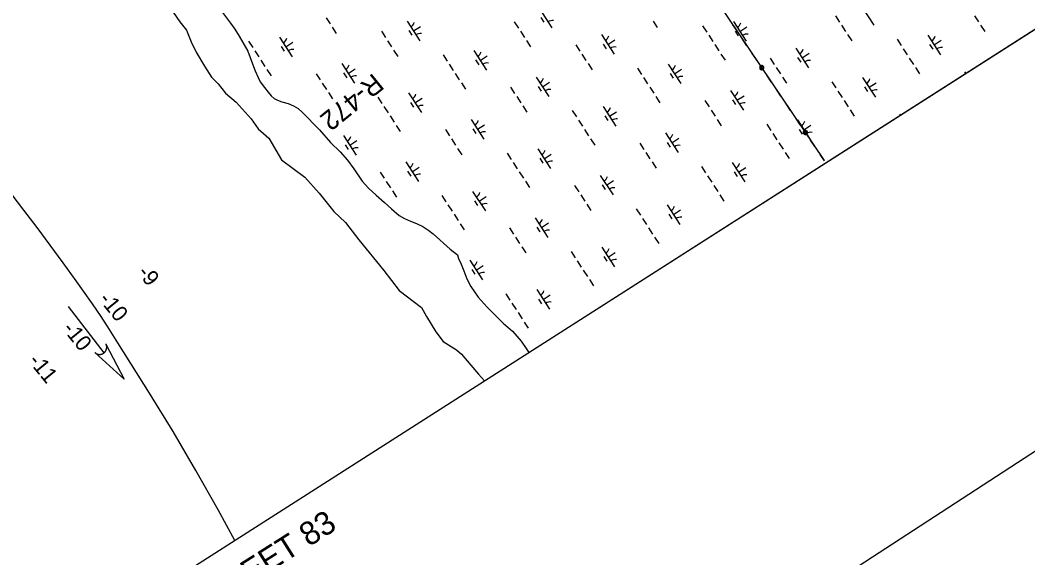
# Model space of a CAD drawing. Extents: x 3953924 to 3974542, y 193747 to 216192.
# Drawn here: x 3968214 to 3970369, y 198304 to 199454 of the extents above; entities that cross this region are included whole.
import ezdxf

# ---------------------------------------------------------------- set-up
doc = ezdxf.new("R2010")
doc.units = 0
for name, color, linetype in [('V-ANNO-SYMB', 7, 'Continuous'), ('V-ANNO-TEXT', 7, 'Continuous'), ('V-GRID-FRAM', 7, 'Continuous'), ('V-RIVR-EDGE', 7, 'Continuous'), ('V-RIVR-RANG', 7, 'Continuous'), ('V-RIVR-RANG-IDEN', 7, 'Continuous'), ('V-STRM-FLOW', 7, 'Continuous'), ('V-TOPO-MINR', 7, 'Continuous'), ('V-UTIL-LINE', 7, 'Continuous'), ('V-WETL-SWMP', 7, 'Continuous')]:
    doc.layers.add(name, color=color, linetype=linetype)

msp = doc.modelspace()

# ---------------------------------------------------------------- linework, layer by layer
at = {"layer": 'V-ANNO-SYMB'}
msp.add_lwpolyline([(3955180.9, 208373.9), (3964205.1, 194510.7), (3973808.1, 200761.7), (3964783.9, 214624.9), (3955180.9, 208373.9)], dxfattribs=at)
at = {"layer": 'V-GRID-FRAM'}
msp.add_lwpolyline([(3964669.3, 213787.9), (3972946, 201072.9), (3966057, 196668.5), (3957950.8, 209463.9), (3964669.3, 213787.9)], dxfattribs=at)
at = {"layer": 'V-RIVR-EDGE'}
msp.add_lwpolyline([(3968541.4, 199470.9), (3968555.6, 199450.7), (3968569.9, 199432.9), (3968579.4, 199408), (3968590, 199385.4), (3968607.8, 199355.7), (3968623.3, 199332), (3968637.5, 199317.7), (3968653, 199297.6), (3968675.5, 199278.6), (3968707.6, 199242.9), (3968723, 199221.6), (3968745.6, 199201.4), (3968772.9, 199155.1), (3968822.7, 199118.3), (3968853.6, 199083.9), (3968884.5, 199044.7), (3968909.4, 199020.9), (3968937.9, 198984.1), (3968991.3, 198918.8), (3969024.6, 198876.1), (3969072, 198839.3), (3969082.7, 198820.3), (3969102.9, 198787.1), (3969118.4, 198766.9), (3969146.8, 198749.1), (3969157.5, 198739.6), (3969177.7, 198715.8), (3969194.3, 198696.8), (3969206.8, 198682.3)], dxfattribs=at)
at = {"layer": 'V-STRM-FLOW'}
msp.add_line((3968316.7, 198841.5), (3968393, 198742.3), dxfattribs=at)
msp.add_lwpolyline([(3968397.3, 198761.3), (3968436.2, 198686.1), (3968373.5, 198743), (3968374.7, 198742.1), (3968375.9, 198741.2), (3968376.4, 198741), (3968376.9, 198740.7), (3968377.5, 198740.4), (3968378, 198740.2), (3968378.5, 198740), (3968379.2, 198739.8), (3968380, 198739.6), (3968380.4, 198739.5), (3968380.9, 198739.4), (3968381.7, 198739.2), (3968382.2, 198739.2), (3968382.8, 198739.1), (3968383.2, 198739.1), (3968383.7, 198739.1), (3968384.2, 198739.1), (3968384.7, 198739.1), (3968385.2, 198739.2), (3968385.7, 198739.2), (3968386.3, 198739.3), (3968386.8, 198739.4), (3968387.3, 198739.5), (3968387.8, 198739.7), (3968388.3, 198739.8), (3968388.7, 198739.9), (3968389, 198740), (3968389.5, 198740.2), (3968389.9, 198740.4), (3968390.4, 198740.6), (3968390.8, 198740.8), (3968391.2, 198741.1), (3968391.7, 198741.3), (3968392, 198741.5), (3968392.5, 198741.9), (3968393, 198742.3), (3968393.2, 198742.4), (3968393.4, 198742.6), (3968393.7, 198742.8), (3968394, 198743.1), (3968394.2, 198743.3), (3968394.5, 198743.5), (3968394.8, 198743.8), (3968394.9, 198744), (3968395.2, 198744.3), (3968395.5, 198744.6), (3968395.6, 198744.8), (3968396, 198745.3), (3968396.2, 198745.6), (3968396.4, 198745.8), (3968396.6, 198746.2), (3968396.8, 198746.5), (3968397, 198746.8), (3968397.2, 198747.2), (3968397.4, 198747.6), (3968397.5, 198747.9), (3968397.7, 198748.1), (3968397.8, 198748.5), (3968397.9, 198748.8), (3968398.1, 198749.2), (3968398.2, 198749.6), (3968398.3, 198749.9), (3968398.5, 198750.4), (3968398.6, 198750.8), (3968398.7, 198751.2), (3968398.7, 198751.6), (3968398.8, 198751.9), (3968398.8, 198752.3), (3968398.9, 198752.8), (3968398.9, 198752.8), (3968398.9, 198753.1), (3968398.9, 198753.3), (3968399, 198753.7), (3968399, 198754.1), (3968399, 198754.4), (3968399, 198754.8), (3968399, 198755.1), (3968398.9, 198755.5), (3968398.9, 198755.8), (3968398.9, 198756.1), (3968398.8, 198756.6), (3968398.8, 198756.9), (3968398.7, 198757.1), (3968398.7, 198757.3), (3968398.6, 198757.6), (3968398.6, 198757.9), (3968398.5, 198758.2), (3968398.4, 198758.5), (3968398.3, 198758.8), (3968398.2, 198759.2), (3968398.1, 198759.5), (3968398, 198759.8), (3968397.8, 198760.3), (3968397.6, 198760.6), (3968397.5, 198760.8), (3968397.4, 198761), (3968397.4, 198761.2)], close=True, dxfattribs=at)
at = {"layer": 'V-TOPO-MINR'}
msp.add_lwpolyline([(3968672.8, 198340.9), (3968637.2, 198406.4), (3968589.9, 198490.7), (3968540.8, 198573.9), (3968490.5, 198656.4), (3968423.1, 198764.1), (3968405.3, 198792.1), (3968387.1, 198819.8), (3968368.5, 198847.1), (3968349.5, 198874.3), (3968333.5, 198896.7), (3968306, 198934.8), (3968278.4, 198972.7), (3968250.3, 199010.3), (3968222.1, 199047.8), (3967951.2, 199403.4)], dxfattribs=at)
at = {"layer": 'V-UTIL-LINE'}
for points in [[(3969933.5, 199153.6), (3965324.7, 205998.6), (3961472.6, 211752)], [(3969747.5, 199429.9), (3969738, 199444)], [(3969768.1, 199399.2), (3969758.6, 199413.3)], [(3969788.8, 199368.5), (3969779.3, 199382.6)], [(3969799.7, 199352.4), (3969799.2, 199351), (3969800.3, 199351.3), (3969800.8, 199352.6), (3969799.8, 199353.7), (3969798.4, 199352.8), (3969797.9, 199350.5), (3969799.7, 199349.4), (3969802, 199350.2), (3969802.5, 199352.4), (3969801.7, 199354.5), (3969799.4, 199355.2), (3969797, 199353.8), (3969795.9, 199349.8), (3969797.2, 199348.6), (3969798.8, 199347.9), (3969800.6, 199347.9), (3969802.2, 199348.6), (3969803.4, 199349.9), (3969804.1, 199351.5), (3969804.1, 199353.2), (3969803.4, 199354.9), (3969802.2, 199356.1), (3969800.5, 199356.8), (3969798.8, 199356.8), (3969797.2, 199356.1), (3969795.9, 199354.8), (3969795.3, 199353.2), (3969795.3, 199351.5), (3969795.9, 199349.8)], [(3969820.1, 199322.1), (3969810.6, 199336.2)], [(3969840.7, 199291.4), (3969831.2, 199305.5)], [(3969861.4, 199260.7), (3969851.9, 199274.8)], [(3969882.1, 199230), (3969872.6, 199244.1)], [(3969893, 199213.8), (3969892.4, 199212.5), (3969893.6, 199212.8), (3969894, 199214.1), (3969893.1, 199215.2), (3969891.6, 199214.3), (3969891.1, 199212), (3969892.9, 199210.9), (3969895.2, 199211.7), (3969895.8, 199213.9), (3969895, 199216), (3969892.7, 199216.6), (3969890.3, 199215.2), (3969889.2, 199211.3), (3969890.5, 199210.1), (3969892.1, 199209.4), (3969893.8, 199209.4), (3969895.5, 199210.1), (3969896.7, 199211.3), (3969897.4, 199213), (3969897.4, 199214.7), (3969896.7, 199216.3), (3969895.4, 199217.6), (3969893.8, 199218.2), (3969892.1, 199218.2), (3969890.4, 199217.6), (3969889.2, 199216.3), (3969888.5, 199214.7), (3969888.5, 199212.9), (3969889.2, 199211.3)], [(3969913.3, 199183.5), (3969903.8, 199197.6)], [(3969934, 199152.9), (3969924.5, 199167)]]:
    msp.add_lwpolyline(points, dxfattribs=at)
at = {"layer": 'V-WETL-SWMP'}
for p, q in [((3969301.7, 198743), (3972946, 201072.9)), ((3968646.4, 199470.3), (3968663.9, 199447.8)), ((3969323.4, 199479.7), (3969350.6, 199437.8)), ((3970011.9, 199485), (3970039.2, 199443.1)), ((3968663.9, 199447.8), (3968673, 199435.1)), ((3968868, 199459.4), (3968876.7, 199446)), ((3969041.1, 199452), (3969068.3, 199410.1)), ((3969270.6, 199450.7), (3969279.4, 199437.3)), ((3969327.3, 199459.6), (3969333.8, 199449.6)), ((3969567.6, 199452), (3969576.3, 199438.6)), ((3969739.1, 199450.9), (3969766.3, 199409)), ((3969957.1, 199463.4), (3969965.9, 199450)), ((3969970.2, 199443.3), (3969979, 199429.8)), ((3970254.6, 199463.7), (3970263.3, 199450.3)), ((3970267.6, 199443.6), (3970276.4, 199430.1)), ((3968673, 199435.1), (3968682.1, 199419.5)), ((3968881.1, 199439.3), (3968889.8, 199425.9)), ((3968986.3, 199430.3), (3968995, 199416.9)), ((3969045, 199431.8), (3969051.5, 199421.8)), ((3969054.7, 199431), (3969069.8, 199440.8)), ((3969283.7, 199430.6), (3969292.4, 199417.2)), ((3969456.8, 199423.1), (3969484.1, 199381.2)), ((3969673.3, 199442), (3969682, 199428.6)), ((3969686.3, 199421.9), (3969695.1, 199408.5)), ((3969743, 199430.8), (3969749.5, 199420.7)), ((3969752.7, 199430), (3969767.8, 199439.8)), ((3969983.3, 199423.1), (3969992.1, 199409.7)), ((3970154.8, 199422.1), (3970182.1, 199380.2)), ((3968682.1, 199419.5), (3968700.4, 199387.6)), ((3968702.4, 199408.9), (3968711.1, 199395.5)), ((3968768.2, 199417.8), (3968795.5, 199375.9)), ((3968781.9, 199396.9), (3968797, 199406.7)), ((3968999.4, 199410.2), (3969008.1, 199396.8)), ((3969296.8, 199410.5), (3969305.5, 199397.1)), ((3969402, 199401.5), (3969410.7, 199388)), ((3969460.7, 199403), (3969467.2, 199392.9)), ((3969470.4, 199402.2), (3969485.5, 199412)), ((3969699.4, 199401.8), (3969708.2, 199388.3)), ((3970089, 199413.2), (3970097.7, 199399.7)), ((3970158.7, 199402), (3970165.2, 199391.9)), ((3970168.4, 199401.1), (3970183.5, 199411)), ((3968700.4, 199387.6), (3968706, 199374.3)), ((3968715.5, 199388.8), (3968724.2, 199375.4)), ((3968772.1, 199397.7), (3968778.7, 199387.6)), ((3969012.5, 199390.1), (3969021.2, 199376.6)), ((3969118.1, 199380.1), (3969126.9, 199366.7)), ((3969184, 199389), (3969211.2, 199347.1)), ((3969415.1, 199381.3), (3969423.8, 199367.9)), ((3969712.5, 199381.6), (3969721.3, 199368.2)), ((3969872.5, 199394.3), (3969899.8, 199352.4)), ((3969886.1, 199373.3), (3969901.2, 199383.2)), ((3970102.1, 199393), (3970110.8, 199379.6)), ((3968706, 199374.3), (3968710.4, 199360.9)), ((3968710.4, 199360.9), (3968716.6, 199345.7)), ((3968728.6, 199368.7), (3968737.3, 199355.3)), ((3968901.7, 199361.2), (3968928.9, 199319.3)), ((3969131.2, 199360), (3969140, 199346.5)), ((3969187.8, 199368.9), (3969194.4, 199358.8)), ((3969197.6, 199368.1), (3969212.7, 199377.9)), ((3969428.2, 199361.2), (3969436.9, 199347.8)), ((3969599.7, 199360.2), (3969626.9, 199318.3)), ((3969817.7, 199372.6), (3969826.5, 199359.2)), ((3969876.4, 199374.2), (3969882.9, 199364.1)), ((3970115.2, 199372.9), (3970123.9, 199359.5)), ((3968716.6, 199345.7), (3968722.8, 199331.2)), ((3968741.7, 199348.6), (3968750.4, 199335.2)), ((3968846.9, 199339.5), (3968855.6, 199326.1)), ((3968905.6, 199341.1), (3968912.1, 199331)), ((3968915.3, 199340.3), (3968930.4, 199350.1)), ((3969144.3, 199339.8), (3969153, 199326.4)), ((3969533.8, 199351.2), (3969542.6, 199337.8)), ((3969603.6, 199340), (3969610.1, 199330)), ((3969613.3, 199339.2), (3969628.4, 199349)), ((3969830.8, 199352.5), (3969839.6, 199339.1)), ((3970128.2, 199352.8), (3970137, 199339.4)), ((3970233.5, 199343.8), (3970235.8, 199340.2)), ((3968722.8, 199331.2), (3968727.1, 199322.5)), ((3968727.1, 199322.5), (3968736.2, 199309.8)), ((3968860, 199319.4), (3968868.7, 199306)), ((3969157.4, 199319.7), (3969166.1, 199306.3)), ((3969317.4, 199332.4), (3969344.6, 199290.5)), ((3969331, 199311.4), (3969346.1, 199321.3)), ((3969546.9, 199331.1), (3969555.7, 199317.7)), ((3969843.9, 199332.4), (3969852.7, 199319)), ((3969949.6, 199322.4), (3969958.3, 199309)), ((3970015.4, 199331.3), (3970042.7, 199289.4)), ((3970029, 199310.4), (3970044.1, 199320.2)), ((3968736.2, 199309.8), (3968744, 199300)), ((3968744, 199300), (3968750.6, 199292)), ((3968873.1, 199299.3), (3968881.8, 199285.9)), ((3969044.5, 199298.3), (3969071.8, 199256.4)), ((3969262.6, 199310.7), (3969271.3, 199297.3)), ((3969321.3, 199312.3), (3969327.8, 199302.2)), ((3969560, 199311), (3969568.8, 199297.6)), ((3969733.1, 199303.6), (3969760.4, 199261.7)), ((3969746.7, 199282.6), (3969761.8, 199292.4)), ((3969962.7, 199302.3), (3969971.4, 199288.9)), ((3970019.3, 199311.2), (3970025.8, 199301.2)), ((3968750.6, 199292), (3968757.2, 199286.8)), ((3968757.2, 199286.8), (3968764.3, 199282.9)), ((3968764.3, 199282.9), (3968773.2, 199279.6)), ((3968773.2, 199279.6), (3968786.8, 199275.8)), ((3968786.8, 199275.8), (3968798.6, 199270.7)), ((3968798.6, 199270.7), (3968808.1, 199265.1)), ((3968978.7, 199289.3), (3968987.5, 199275.9)), ((3969048.4, 199278.1), (3969055, 199268.1)), ((3969058.2, 199277.3), (3969073.3, 199287.1)), ((3969275.7, 199290.6), (3969284.4, 199277.2)), ((3969573.1, 199290.9), (3969581.9, 199277.5)), ((3969678.3, 199281.9), (3969687.1, 199268.5)), ((3969737, 199283.4), (3969743.5, 199273.4)), ((3969975.7, 199282.2), (3969984.5, 199268.8)), ((3968808.1, 199265.1), (3968817.1, 199257.1)), ((3968817.1, 199257.1), (3968854.3, 199219.2)), ((3968991.8, 199269.2), (3969000.5, 199255.8)), ((3969288.8, 199270.5), (3969297.5, 199257.1)), ((3969394.4, 199260.5), (3969403.2, 199247.1)), ((3969460.3, 199269.4), (3969487.5, 199227.5)), ((3969464.2, 199249.3), (3969470.7, 199239.2)), ((3969473.9, 199248.5), (3969489, 199258.3)), ((3969691.4, 199261.8), (3969700.2, 199248.4)), ((3969988.8, 199262.1), (3969997.6, 199248.7)), ((3970094, 199253), (3970095.6, 199250.6)), ((3969004.9, 199249.1), (3969013.6, 199235.7)), ((3969018, 199229), (3969026.7, 199215.6)), ((3969178, 199241.6), (3969205.2, 199199.7)), ((3969191.6, 199220.7), (3969206.7, 199230.5)), ((3969407.5, 199240.4), (3969416.3, 199227)), ((3969704.5, 199241.7), (3969713.2, 199228.2)), ((3969810.2, 199231.7), (3969818.9, 199218.3)), ((3969876, 199240.6), (3969903.3, 199198.7)), ((3969889.6, 199219.6), (3969904.7, 199229.5)), ((3968854.3, 199219.2), (3968877.8, 199192.2)), ((3968905.1, 199207.5), (3968932.4, 199165.6)), ((3969123.2, 199220), (3969131.9, 199206.6)), ((3969181.9, 199221.5), (3969188.4, 199211.5)), ((3969420.6, 199220.3), (3969429.4, 199206.9)), ((3969593.7, 199212.8), (3969621, 199170.9)), ((3969823.3, 199211.6), (3969832, 199198.1)), ((3969879.9, 199220.5), (3969886.4, 199210.4)), ((3968877.8, 199192.2), (3968898.2, 199172.1)), ((3968909, 199187.4), (3968915.6, 199177.3)), ((3968918.8, 199186.6), (3968933.9, 199196.4)), ((3969136.3, 199199.9), (3969145, 199186.4)), ((3969433.7, 199200.2), (3969442.4, 199186.7)), ((3969538.9, 199191.1), (3969547.7, 199177.7)), ((3969597.6, 199192.7), (3969604.1, 199182.6)), ((3969607.3, 199191.9), (3969622.4, 199201.7)), ((3969836.3, 199191.4), (3969845.1, 199178)), ((3968898.2, 199172.1), (3968913.8, 199154.8)), ((3969149.4, 199179.7), (3969158.1, 199166.3)), ((3969255, 199169.8), (3969263.8, 199156.3)), ((3969320.9, 199178.7), (3969348.1, 199136.8)), ((3969334.5, 199157.7), (3969349.6, 199167.6)), ((3969552, 199171), (3969560.7, 199157.6)), ((3969849.4, 199171.3), (3969858.2, 199157.9)), ((3968913.8, 199154.8), (3968927.7, 199135.8)), ((3969038.6, 199150.9), (3969065.8, 199109)), ((3969268.1, 199149.6), (3969276.9, 199136.2)), ((3969324.8, 199158.6), (3969331.3, 199148.5)), ((3969565.1, 199150.9), (3969573.8, 199137.5)), ((3969736.6, 199149.9), (3969763.8, 199107.9)), ((3969954.6, 199162.3), (3969955.5, 199161)), ((3968927.7, 199135.8), (3968945.3, 199109.8)), ((3968983.8, 199129.2), (3968992.5, 199115.8)), ((3969042.5, 199130.8), (3969049, 199120.7)), ((3969052.2, 199129.9), (3969067.3, 199139.8)), ((3969281.2, 199129.5), (3969290, 199116.1)), ((3969454.3, 199122.1), (3969481.6, 199080.2)), ((3969670.8, 199140.9), (3969679.5, 199127.5)), ((3969683.8, 199120.8), (3969692.6, 199107.4)), ((3969740.5, 199129.7), (3969747, 199119.7)), ((3969750.2, 199128.9), (3969765.3, 199138.7)), ((3968945.3, 199109.8), (3968959.1, 199094.8)), ((3968996.9, 199109.1), (3969005.6, 199095.7)), ((3969294.3, 199109.4), (3969303, 199096)), ((3969399.5, 199100.4), (3969408.3, 199087)), ((3969458.2, 199101.9), (3969464.7, 199091.9)), ((3969467.9, 199101.1), (3969483, 199110.9)), ((3969696.9, 199100.7), (3969705.7, 199087.3)), ((3968959.1, 199094.8), (3968975.3, 199080)), ((3968975.3, 199080), (3968993.2, 199063.9)), ((3969010, 199089), (3969018.7, 199075.6)), ((3969115.6, 199079), (3969124.4, 199065.6)), ((3969181.5, 199087.9), (3969208.7, 199046)), ((3969195.1, 199067), (3969210.2, 199076.8)), ((3969412.6, 199080.3), (3969421.3, 199066.9)), ((3969710, 199080.6), (3969718.8, 199067.2)), ((3968993.2, 199063.9), (3969007.6, 199050.2)), ((3969128.7, 199058.9), (3969137.5, 199045.5)), ((3969185.4, 199067.8), (3969191.9, 199057.7)), ((3969425.7, 199060.2), (3969434.4, 199046.8)), ((3969597.2, 199059.1), (3969624.4, 199017.2)), ((3969815.2, 199071.6), (3969815.3, 199071.4)), ((3969007.6, 199050.2), (3969024.4, 199035.9)), ((3969024.4, 199035.9), (3969035.6, 199029.7)), ((3969141.8, 199038.8), (3969150.5, 199025.4)), ((3969531.3, 199050.2), (3969540.1, 199036.8)), ((3969601.1, 199039), (3969607.6, 199028.9)), ((3969610.8, 199038.2), (3969625.9, 199048)), ((3969035.6, 199029.7), (3969048.7, 199024.1)), ((3969048.7, 199024.1), (3969061.1, 199019.1)), ((3969061.1, 199019.1), (3969075.3, 199013)), ((3969075.3, 199013), (3969087.8, 199003.9)), ((3969154.9, 199018.7), (3969163.6, 199005.3)), ((3969314.9, 199031.3), (3969342.2, 198989.4)), ((3969328.5, 199010.4), (3969343.6, 199020.2)), ((3969544.4, 199030.1), (3969553.2, 199016.7)), ((3969087.8, 199003.9), (3969096.8, 198997)), ((3969096.8, 198997), (3969133.3, 198964.4)), ((3969260.1, 199009.6), (3969268.8, 198996.2)), ((3969318.8, 199011.2), (3969325.3, 199001.1)), ((3969557.5, 199009.9), (3969566.3, 198996.5)), ((3969273.2, 198989.5), (3969281.9, 198976.1)), ((3969286.3, 198969.4), (3969295, 198956)), ((3969570.6, 198989.8), (3969579.4, 198976.4)), ((3969133.3, 198964.4), (3969148.8, 198951.9)), ((3969148.8, 198951.9), (3969151.3, 198944.3)), ((3969391.9, 198959.4), (3969400.7, 198946)), ((3969457.8, 198968.4), (3969485, 198926.5)), ((3969461.7, 198948.2), (3969468.2, 198938.2)), ((3969471.4, 198947.4), (3969486.5, 198957.2)), ((3969151.3, 198944.3), (3969156.9, 198932.1)), ((3969156.9, 198932.1), (3969162.5, 198917.6)), ((3969175.5, 198940.6), (3969202.7, 198898.7)), ((3969189.1, 198919.6), (3969204.2, 198929.4)), ((3969405, 198939.3), (3969413.8, 198925.9)), ((3969162.5, 198917.6), (3969169.3, 198900.7)), ((3969179.4, 198920.4), (3969185.9, 198910.4)), ((3969418.1, 198919.2), (3969426.9, 198905.8)), ((3969169.3, 198900.7), (3969177.3, 198884.5)), ((3969177.3, 198884.5), (3969193, 198861.3)), ((3969431.2, 198899.1), (3969440, 198885.7)), ((3969193, 198861.3), (3969212.3, 198840.1)), ((3969252.5, 198868.7), (3969261.3, 198855.3)), ((3969318.4, 198877.6), (3969345.6, 198835.7)), ((3969332, 198856.7), (3969347.1, 198866.5)), ((3969212.3, 198840.1), (3969231.5, 198821.1)), ((3969265.6, 198848.6), (3969274.4, 198835.2)), ((3969322.3, 198857.5), (3969328.8, 198847.4)), ((3969231.5, 198821.1), (3969247, 198806.2)), ((3969278.7, 198828.5), (3969287.5, 198815)), ((3969247, 198806.2), (3969266.8, 198788.5)), ((3969291.8, 198808.3), (3969300.5, 198794.9)), ((3969266.8, 198788.5), (3969285.5, 198767.2)), ((3969285.5, 198767.2), (3969297, 198749.3)), ((3969297, 198749.3), (3969301.7, 198743))]:
    msp.add_line(p, q, dxfattribs=at)
for centre, start, end in [((3969039.8, 199454.3), 302.2901, 343.8338), ((3969352.3, 199435.8), 82.2901, 123.8337), ((3969737.8, 199453.2), 302.2901, 343.8338), ((3969070, 199408), 82.2901, 123.8337), ((3969768, 199406.9), 82.2901, 123.8337), ((3968767, 199420.2), 302.2901, 343.8338), ((3969455.5, 199425.5), 302.2901, 343.8338), ((3970153.6, 199424.4), 302.2901, 343.8338), ((3968797.1, 199373.9), 82.2901, 123.8337), ((3969182.7, 199391.3), 302.2901, 343.8338), ((3969485.7, 199379.2), 82.2901, 123.8337), ((3969871.3, 199396.6), 302.2901, 343.8338), ((3970183.7, 199378.1), 82.2901, 123.8337), ((3968900.4, 199363.5), 302.2901, 343.8338), ((3969212.9, 199345), 82.2901, 123.8337), ((3969598.4, 199362.5), 302.2901, 343.8338), ((3969901.4, 199350.3), 82.2901, 123.8337), ((3968930.6, 199317.2), 82.2901, 123.8337), ((3969316.1, 199334.7), 302.2901, 343.8338), ((3969628.6, 199316.2), 82.2901, 123.8337), ((3970014.2, 199333.7), 302.2901, 343.8338), ((3969043.3, 199300.6), 302.2901, 343.8338), ((3969346.3, 199288.4), 82.2901, 123.8337), ((3969731.9, 199305.9), 302.2901, 343.8338), ((3970044.3, 199287.4), 82.2901, 123.8337), ((3969073.5, 199254.3), 82.2901, 123.8337), ((3969762, 199259.6), 82.2901, 123.8337), ((3969459, 199271.8), 302.2901, 343.8338), ((3969176.7, 199244), 302.2901, 343.8338), ((3969489.2, 199225.5), 82.2901, 123.8337), ((3969874.7, 199242.9), 302.2901, 343.8338), ((3969206.9, 199197.7), 82.2901, 123.8337), ((3969592.5, 199215.1), 302.2901, 343.8338), ((3969904.9, 199196.6), 82.2901, 123.8337), ((3968903.9, 199209.8), 302.2901, 343.8338), ((3969622.6, 199168.8), 82.2901, 123.8337), ((3968934, 199163.5), 82.2901, 123.8337), ((3969319.6, 199181), 302.2901, 343.8338), ((3969037.3, 199153.2), 302.2901, 343.8338), ((3969349.8, 199134.7), 82.2901, 123.8337), ((3969735.3, 199152.2), 302.2901, 343.8338), ((3969067.5, 199106.9), 82.2901, 123.8337), ((3969765.5, 199105.9), 82.2901, 123.8337), ((3969453, 199124.4), 302.2901, 343.8338), ((3969180.2, 199090.3), 302.2901, 343.8338), ((3969483.2, 199078.1), 82.2901, 123.8337), ((3969210.4, 199044), 82.2901, 123.8337), ((3969595.9, 199061.4), 302.2901, 343.8338), ((3969313.6, 199033.6), 302.2901, 343.8338), ((3969626.1, 199015.1), 82.2901, 123.8337), ((3969343.8, 198987.4), 82.2901, 123.8337), ((3969456.5, 198970.7), 302.2901, 343.8338), ((3969174.2, 198942.9), 302.2901, 343.8338), ((3969486.7, 198924.4), 82.2901, 123.8337), ((3969204.4, 198896.6), 82.2901, 123.8337), ((3969317.1, 198879.9), 302.2901, 343.8338), ((3969347.3, 198833.6), 82.2901, 123.8337)]:
    msp.add_arc(centre, 17.6, start, end, dxfattribs=at)

# ---------------------------------------------------------------- texts
at = {"layer": 'V-ANNO-TEXT'}
msp.add_text('JOINS SHEET 83', height=50, rotation=32.3552, dxfattribs=at).set_placement((3968445.2, 198082))
at = {"layer": 'V-RIVR-RANG'}
for s, p in [('-9', (3968463.2, 198913.2)), ('-10', (3968380.5, 198856.4)), ('-10', (3968302.9, 198793.3)), ('-11', (3968230, 198724.5))]:
    msp.add_text(s, height=33.5, rotation=309.1325, dxfattribs=at).set_placement(p)
at = {"layer": 'V-RIVR-RANG-IDEN'}
msp.add_text('R-472  ', height=41.5, rotation=219.0244, dxfattribs=at).set_placement((3968969.2, 199342.3))

doc.saveas('drawing.dxf')
